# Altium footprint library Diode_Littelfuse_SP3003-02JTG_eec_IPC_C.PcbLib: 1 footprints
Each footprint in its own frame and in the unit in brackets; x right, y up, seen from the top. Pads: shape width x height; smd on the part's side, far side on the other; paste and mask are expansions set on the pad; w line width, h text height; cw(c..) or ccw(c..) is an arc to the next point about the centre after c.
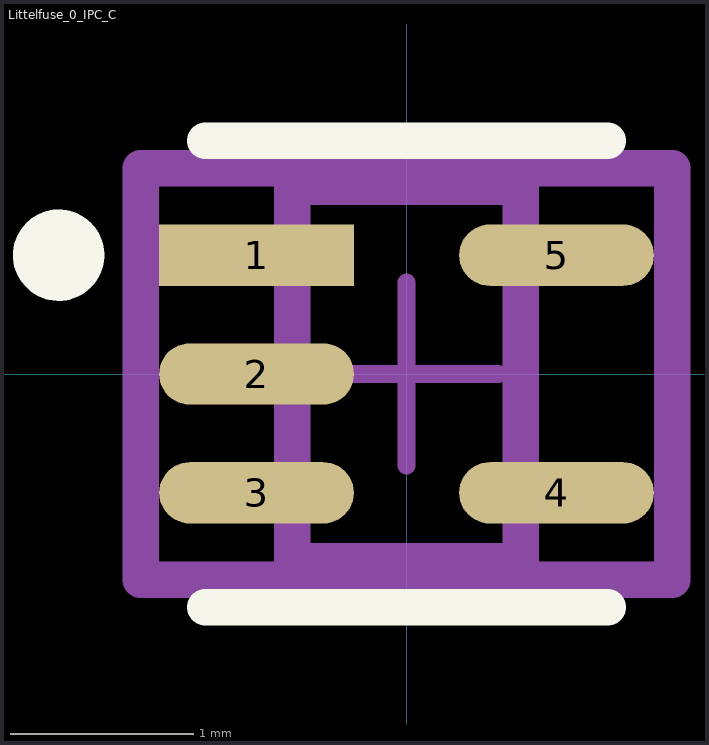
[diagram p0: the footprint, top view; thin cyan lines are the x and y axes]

## Littelfuse_0_IPC_C [mm]
pads (5):
  rect 1.066x0.336 smd paste+0 mask+0: 1(-0.82,0.65)
  rrect100% 1.066x0.336 smd paste+0 mask+0: 2(-0.82,0) 3(-0.82,-0.65) 4(0.82,-0.65) 5(0.82,0.65)
Top Overlay:
  circle w0.25: c-1.903,0.65 r0.125
  lines w0.2: -1.1,-1.275 1.1,-1.275 ; -1.1,1.275 1.1,1.275
Mechanical 10:
  lines w0.2: -1.453,-1.125 1.453,-1.125 1.453,1.125 -1.453,1.125 -1.453,-1.125
  text ".Designator" at 0,0 h1
Mechanical 12:
  lines w0.2: -0.625,-1.025 0.625,-1.025 0.625,1.025 -0.625,1.025 -0.625,-1.025
Mechanical 15:
  lines w0.1: -0.5,0 0.5,0 ; 0,-0.5 0,0.5
  lines w0.2: -1.453,-1.125 1.453,-1.125 1.453,1.125 -1.453,1.125 -1.453,-1.125
3D body "Diode_Littelfuse_SP3003-02JTG_eec.STEP": height 0.25, standoff 0, extent -1.453,-1.125 1.453,1.125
